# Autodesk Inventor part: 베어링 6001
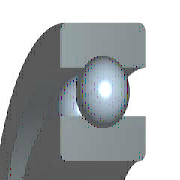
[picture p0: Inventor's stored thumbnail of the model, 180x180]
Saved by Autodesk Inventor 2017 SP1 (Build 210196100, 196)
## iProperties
Created: 2012-02
Part Number: 베어링 6001
Material: 강철, 연강
Description: 깊은 그루브 볼 베어링
Document SubType Name: Modeling
Standard: KS B 2023
Designer: mduedu
Standards Organization: KS
Language: ko-KR
Size Designation: 6001 - 12 x 28 x 8
Categories: <MemberInstance><Categories><Category DisplayName="샤프트 부품" InternalName="7f7aeb1f-a693-4053-b835-cee3144e0d98" Mnemonic="SHFT"><Category DisplayName="베어링" Inter
Density: 7.86 g/cm^3
Mass: 21.4855 g
Surface Area: 31.1809 cm^2
Volume: 2.73352 cm^3
Appearance: 노란색
IsCustomPart: 1
Author: mduedu
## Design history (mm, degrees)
sketch "스케치" dims "d0" = 4.16 (= -0.26 x WD + 0.26 x BD)
  geometry: L1 (1.92, 10)-(6.08, 10); L2 (4, 10)-(4, 7.92); L3 (4, 10)-(4, 12.08); L4 (2.454, 8.608)-(0, 8.608); L5 (0, 6)-(8, 6); L6 (2.454, 11.392)-(0, 11.392); L7 (0, 14)-(8, 14); L8 (8, 6)-(8, 8.608); L9 (5.546, 8.608)-(8, 8.608); L10 (5.546, 11.392)-(8, 11.392); L11 (8, 14)-(8, 11.392); L12 (-1.4, 0)-(8.4, 0) reference; L13 (0, -0.3)-(0, 5.3) reference
  constraints: 22 end point, 4 point on line, 2 collinear, 2 perpendicular, 2 symmetric about line, 1 midpoint, 1 parallel, 14 other
  dimensions: "d9" = 12 diameter of L5 L12 (= WD); "d11" = 28 diameter of L7 L12 (= BD); "d12" = 8 distance between parallel lines of L8 L13 (= KB); "d13" = 17.216 diameter of L9 L12 (= 0.326 x BD + 0.674 x WD)
revolve "본체" stored, may be unused: angle "d6" = 90 deg
revolve "볼" stored, may be unused: angle "d7" = 90 deg
pattern_circular "IDS_ARRAYBALL[SIMPL:T]" dims angle "d3" = 360 deg
body "Solid1"
fillet "모깎기1" dims "d1" = 0.3 (= KRS)
other parameters: "WD" = 12 [user parameter; used in 5 equation terms], "BD" = 28 [user parameter; used in 5 equation terms], "KB" = 8 [user parameter; used in 1 equation term], "KRS" = 0.3 [user parameter; used in 1 equation term], "d4" = 0, "d5" = 0, "d8" = 0, "d14" = 0, "d15" = 0, "BBA" = 0 [user parameter], "BC0" = 2360000 [user parameter], "BC" = 5070000 [user parameter], "BR" = 14 (= 0.5 x BD) [user parameter], "WR" = 6 (= 0.5 x WD) [user parameter]
